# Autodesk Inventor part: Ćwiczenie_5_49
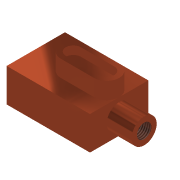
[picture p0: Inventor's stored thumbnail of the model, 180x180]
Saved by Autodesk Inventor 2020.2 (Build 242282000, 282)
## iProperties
Created: 2005-05
Part Number: Ćwiczenie_5_49
Document SubType Name: Modeling
Designer: F.Stasiak
Manufacturer: Standard
Standards Organization: Custom
Density: 1 g/cm^3
Material: Ogólny
Appearance: Miedź — polerowana
Manager: www.cadconsulting.pl
Company: Fabian Stasiak CAD Consulting
Author: F.Stasiak
Subject: Zbiór ćwiczeń. Autodesk Inventor 2020. Kurs podstawowy
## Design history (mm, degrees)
sketch "Szkic1"
  geometry: L1 (-50, 35)-(50, 35); L2 (50, 35)-(50, -35); L3 (50, -35)-(-50, -35); L4 (-50, -35)-(-50, 35); L5 (0, 35)-(0, -35); 2 further points
  constraints: 10 end point, 3 midpoint, 2 parallel, 1 coincident, 1 horizontal, 1 perpendicular
  dimensions: "d0" = 100 distance of L2.end L3.end; "d1" = 70 distance of L3.end L1.start
extrude "Wyciągnięcie proste1" new body sketch "Szkic1" stored distance "d2" = 40; taper "d3" = 0 deg
sketch "Szkic2"
  geometry: L1 (-40, 70)-(-40, 0) reference; L2 (0, 0)-(0, 70) reference; L3 (-40, 35)-(0, 35); C1 r 15 at (-20, 35)
  constraints: 3 midpoint, 2 end point, 1 centre point
  dimensions: "d4" = 30 diameter of C1
extrude "Wyciągnięcie proste2" join sketch "Szkic2" distance "d5" = 30; taper "d6" = 0 deg
sketch "Szkic3"
  geometry: L1 (50, -35)-(-50, -35) reference; L2 (-50, 35)-(50, 35) reference; L3 (0, -35)-(0, 35); L4 (-5, 15)-(35, 15); L5 (35, -15)-(-5, -15); L6 (-5, 0)-(35, 0); A1 r 15 centre (35, 0) between (35, -15) and (35, 15); A2 r 15 centre (-5, 0) between (-5, 15) and (-5, -15); 2 further points
  constraints: 8 end point, 4 point on circle, 4 tangent, 3 midpoint, 2 centre point, 2 perpendicular, 1 parallel, 1 point on line
  dimensions: "d7" = 40 distance of L5.start L5.end; "d8" = 15 radius of A1; "d26" = 5 distance of L6.start point (0, 0)
extrude "Wyciągnięcie proste3" join sketch "Szkic3" distance "d9" = 20; taper "d10" = 0 deg
sketch "Szkic4"
  geometry: L1 (-5, 15)-(35, 15) reference; L2 (35, -15)-(-5, -15) reference; L3 (-5, 9)-(35, 9); L4 (35, -9)-(-5, -9); A1 r 15 centre (35, 0) between (35, -15) and (35, 15) reference; A2 r 15 centre (-5, 0) between (-5, 15) and (-5, -15) reference; A3 r 9 centre (-5, 0) between (-5, 9) and (-5, -9); A4 r 9 centre (35, 0) between (35, -9) and (35, 9)
  constraints: 4 end point, 4 point on circle, 2 centre point, 3 other
  dimensions: "d11" = 6 distance between parallel lines of L1 L3
extrude "Wyciągnięcie proste4" cut sketch "Szkic4" distance "d12" = 10; taper "d13" = 0 deg
sketch "Szkic7"
  geometry: C1 r 15 at (0, 0) reference
hole "Otwór2" sketch "Szkic7" at (0, 0) diameter "d73" = 17.294; stored, may be unused: countersink angle "d77" = 90 deg, drill point angle "d79" = 118 deg; dims "d74" = 6, "d75" = 4, "d76" = 2, "d78" = 8
node "Bryła1"
node "Korpusy bryłowe"
node "Korpusy powierzchniowe"
node "Pętla rzutowana1"
